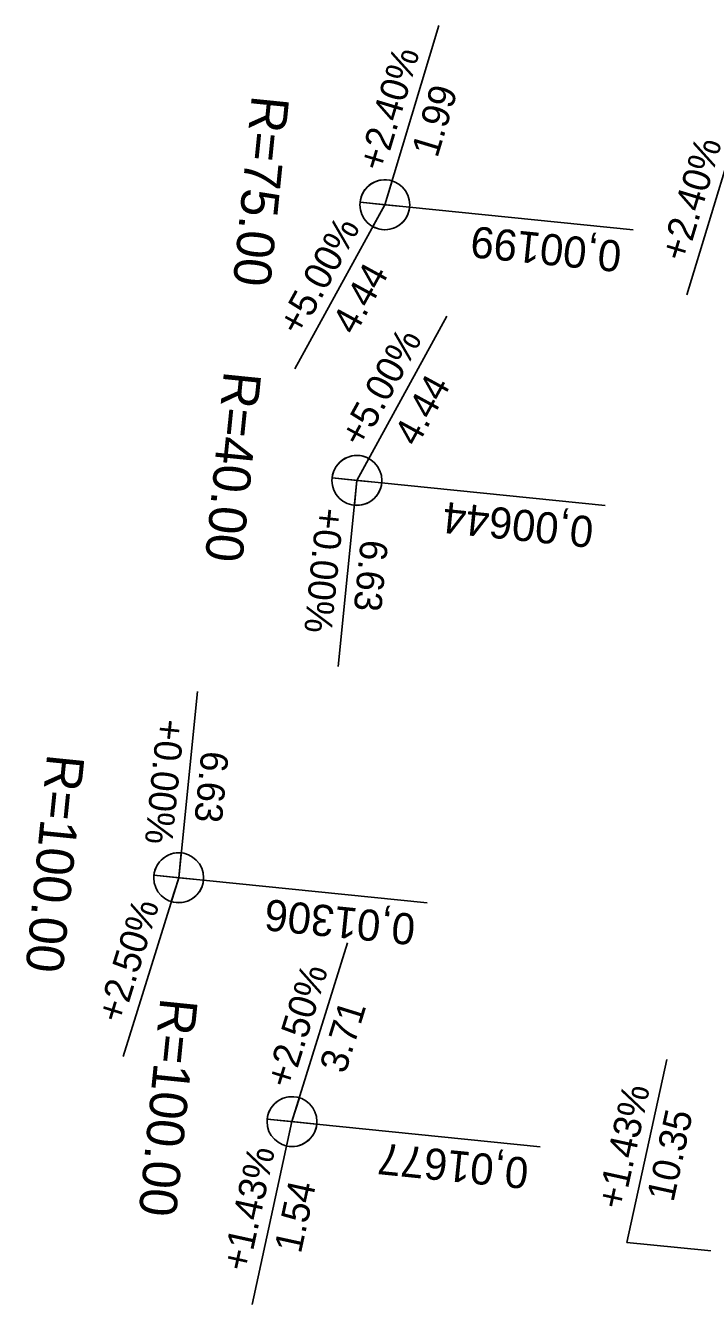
# Model space of a CAD drawing. Extents: x -747612 to -743169, y -1131726 to -1127091.
# Drawn here: x -747612.43 to -747601.59, y -1131715.1 to -1131694.59 of the extents above; entities that cross this region are included whole.
import ezdxf

# ---------------------------------------------------------------- set-up
doc = ezdxf.new("R2010")
doc.units = 0
doc.layers.add('SKLONOVNIKY', color=7, linetype='Continuous')

# ---------------------------------------------------------------- blocks, each defined once
blk = doc.blocks.new('AeccTickCircle')
blk.add_circle((0, 0), 0.5)

msp = doc.modelspace()

# ---------------------------------------------------------------- linework, layer by layer
at = {"layer": 'SKLONOVNIKY'}
for p, q in [((-747606.677, -1131697.463), (-747605.811, -1131694.59)), ((-747600.968, -1131696.038), (-747601.835, -1131698.91)), ((-747606.677, -1131697.463), (-747608.117, -1131700.095)), ((-747602.697, -1131697.866), (-747607.075, -1131697.422)), ((-747607.124, -1131701.883), (-747605.685, -1131699.251)), ((-747603.145, -1131702.286), (-747607.522, -1131701.843)), ((-747607.124, -1131701.883), (-747607.427, -1131704.868)), ((-747609.981, -1131708.254), (-747609.678, -1131705.27)), ((-747606.001, -1131708.657), (-747610.379, -1131708.214)), ((-747609.981, -1131708.254), (-747610.87, -1131711.12)), ((-747608.165, -1131712.165), (-747607.276, -1131709.3)), ((-747602.797, -1131714.101), (-747602.157, -1131711.17)), ((-747604.186, -1131712.568), (-747608.563, -1131712.125)), ((-747608.165, -1131712.165), (-747608.805, -1131715.096)), ((-747598.817, -1131714.503), (-747602.797, -1131714.101))]:
    msp.add_line(p, q, dxfattribs=at)
for points in [[(-747607.075, -1131697.422), (-747606.677, -1131697.463), (-747606.561, -1131697.08)], [(-747606.279, -1131697.503), (-747606.677, -1131697.463), (-747606.869, -1131697.814)], [(-747607.522, -1131701.843), (-747607.124, -1131701.883), (-747606.932, -1131701.532)], [(-747606.726, -1131701.924), (-747607.124, -1131701.883), (-747607.165, -1131702.281)], [(-747610.379, -1131708.214), (-747609.981, -1131708.254), (-747609.94, -1131707.856)], [(-747609.583, -1131708.295), (-747609.981, -1131708.254), (-747610.099, -1131708.636)], [(-747608.563, -1131712.125), (-747608.165, -1131712.165), (-747608.047, -1131711.783)], [(-747607.767, -1131712.205), (-747608.165, -1131712.165), (-747608.251, -1131712.556)]]:
    msp.add_lwpolyline(points, dxfattribs=at)
for centre, start, end in [((-747606.677, -1131697.463), 73.2181, 174.2192), ((-747606.677, -1131697.463), 241.32, 354.2192), ((-747607.124, -1131701.883), 61.32, 174.2192), ((-747607.124, -1131701.883), 264.2192, 354.2192), ((-747609.981, -1131708.254), 84.2192, 174.2192), ((-747609.981, -1131708.254), 252.7625, 354.2192), ((-747608.165, -1131712.165), 72.7625, 174.2192), ((-747608.165, -1131712.165), 257.6852, 354.2192)]:
    msp.add_arc(centre, 0.4, start, end, dxfattribs=at)

# ---------------------------------------------------------------- block references
at = {"layer": 'SKLONOVNIKY', "xscale": 0.8000000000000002, "yscale": -0.8, "rotation": 174.2192274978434}
for p in [(-747606.677, -1131697.463), (-747607.124, -1131701.883), (-747609.981, -1131708.254), (-747608.165, -1131712.165)]:
    msp.add_blockref('AeccTickCircle', p, dxfattribs=at)

# ---------------------------------------------------------------- texts
at = {"layer": 'SKLONOVNIKY'}
for s, height, rotation, p in [('+2.40%', 0.44, 73.2181, (-747606.696, -1131696.95)), ('1.99', 0.44, 73.2181, (-747605.836, -1131696.725)), ('R=75.00', 0.6, 264.2192, (-747608.806, -1131695.696)), ('+2.40%', 0.44, 73.2181, (-747601.853, -1131698.397)), ('+5.00%', 0.44, 61.32, (-747608.029, -1131699.589)), ('0,00199', 0.5, 174.2192, (-747602.866, -1131698.048)), ('4.44', 0.44, 61.32, (-747607.157, -1131699.57)), ('+5.00%', 0.44, 61.32, (-747607.037, -1131701.378)), ('R=40.00', 0.6, 264.2192, (-747609.253, -1131700.117)), ('4.44', 0.44, 61.32, (-747606.165, -1131701.359)), ('0,00644', 0.5, 174.2192, (-747603.314, -1131702.469)), ('+0.00%', 0.44, 264.2192, (-747607.768, -1131702.306)), ('6.63', 0.44, 264.2192, (-747607.061, -1131702.822)), ('+0.00%', 0.44, 264.2192, (-747610.322, -1131705.693)), ('R=100.00', 0.6, 264.2192, (-747612.086, -1131706.256)), ('6.63', 0.44, 264.2192, (-747609.615, -1131706.208)), ('+2.50%', 0.44, 72.7625, (-747610.884, -1131710.607)), ('0,01306', 0.5, 174.2192, (-747606.17, -1131708.84)), ('+2.50%', 0.44, 72.7625, (-747608.18, -1131711.652)), ('R=100.00', 0.6, 264.2192, (-747610.271, -1131710.167)), ('3.71', 0.44, 72.7625, (-747607.312, -1131711.412)), ('+1.43%', 0.44, 77.6852, (-747602.856, -1131713.591)), ('10.35', 0.44, 77.6852, (-747602.053, -1131713.468)), ('0,01677', 0.5, 174.2192, (-747604.355, -1131712.75)), ('+1.43%', 0.44, 77.6852, (-747608.864, -1131714.586)), ('1.54', 0.44, 77.6852, (-747608.024, -1131714.294))]:
    msp.add_text(s, height=height, rotation=rotation, dxfattribs=at).set_placement(p)

doc.saveas('drawing.dxf')
